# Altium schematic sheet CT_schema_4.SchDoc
size 287 x 163 mm
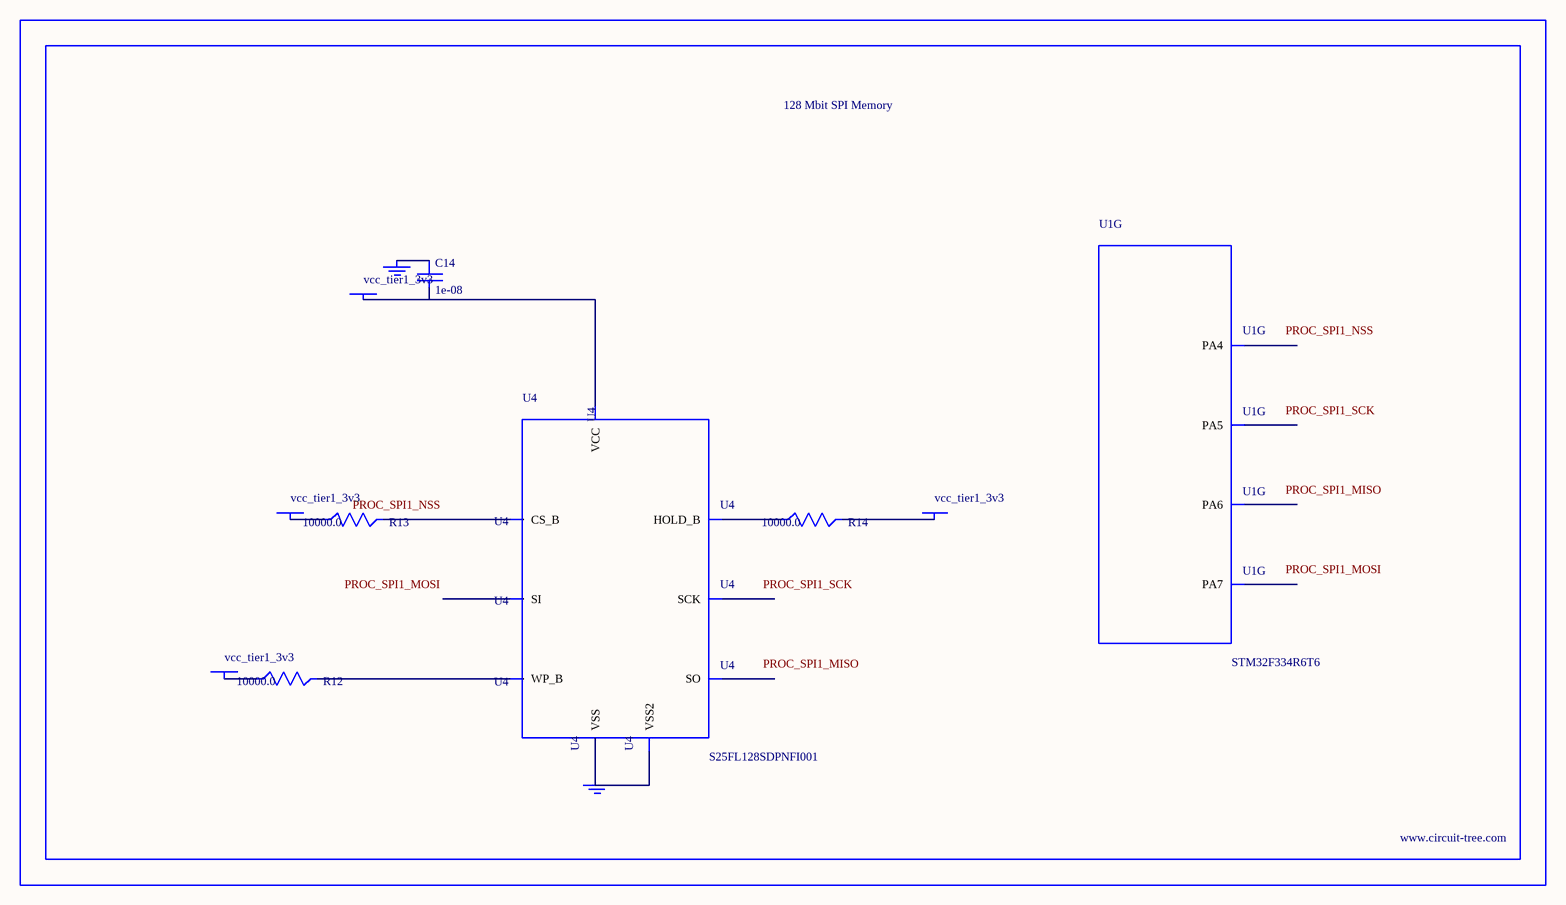
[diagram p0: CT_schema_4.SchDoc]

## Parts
BORDER3  (no value)
C14  1e-08  [C0402]
GND_INSTANCE_3_0  (no value)
GND_INSTANCE_3_1  (no value)
POWER_INSTANCE_3_0  vcc_tier1_3v3
POWER_INSTANCE_3_1  vcc_tier1_3v3
POWER_INSTANCE_3_2  vcc_tier1_3v3
POWER_INSTANCE_3_3  vcc_tier1_3v3
R12  10000.0  [R0603]
R13  10000.0  [R0603]
R14  10000.0  [R0603]
U1  STM32F334R6T6  [LQFP64]  (part G of 7)
U4  S25FL128SDPNFI001  [WNG008]

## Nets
NetC14_1: C14.1 GND_INSTANCE_3_0.0(GND)
NetC14_2: C14.2 POWER_INSTANCE_3_3.0(PWR) U4.8(VCC)
NetGND_INSTANCE_3_1_0: GND_INSTANCE_3_1.0(GND) U4.4(VSS) U4.PAD(VSS2)
NetPOWER_INSTANCE_3_0_0: POWER_INSTANCE_3_0.0(PWR) R13.1
NetPOWER_INSTANCE_3_1_0: POWER_INSTANCE_3_1.0(PWR) R12.1
NetPOWER_INSTANCE_3_2_0: POWER_INSTANCE_3_2.0(PWR) R14.2
NetR12_2: R12.2 U4.3(WP_B)
NetR13_2: R13.2 U4.1(CS_B)
NetR14_1: R14.1 U4.7(HOLD_B)

Not connected (* = marked no-connect by the designer): U1 20(PA4) 21(PA5) 22(PA6) 23(PA7); U4 2(SO) 5(SI) 6(SCK)

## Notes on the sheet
- Labels drawn without touching a wire or pin: PROC_SPI1_MISO, PROC_SPI1_MOSI, PROC_SPI1_NSS, PROC_SPI1_SCK

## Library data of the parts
BORDER3 = BORDER_PAGE3
C14 = C0402C103K3RAC
GND_INSTANCE_3_0 GND_INSTANCE_3_1 = GND
POWER_INSTANCE_3_0-POWER_INSTANCE_3_3 = PWR
R12-R14 = RC0603JR-0710KL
